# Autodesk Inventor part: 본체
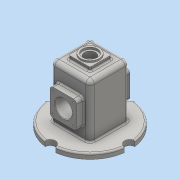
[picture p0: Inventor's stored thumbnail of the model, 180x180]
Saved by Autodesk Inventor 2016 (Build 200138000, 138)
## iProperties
Created: 2018-07
Part Number: 본체
Material: 일반
Document SubType Name: Modeling
Designer: 2-PC06
Density: 1 g/cm^3
Appearance: 기본값
Author: 2-PC06
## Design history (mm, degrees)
sketch "스케치1"
  geometry: C1 r 75 at (0, 0); 1 further point
  constraints: 1 centre point, 1 coincident
  dimensions: "d0" = 150 diameter of C1
extrude "돌출1" new body sketch "스케치1" distance "d1" = 10; taper "d2" = 0 deg
sketch "스케치2"
  geometry: L1 (-37, 37)-(37, 37); L2 (37, 37)-(37, -37); L3 (37, -37)-(-37, -37); L4 (-37, -37)-(-37, 37); L5 (-37, 37)-(37, -37); L6 (37, 37)-(-37, -37); 1 further point
  constraints: 12 end point, 2 midpoint, 2 parallel, 1 horizontal, 1 perpendicular
  dimensions: "d3" = 74 distance of L1.start L1.end; "d4" = 74 distance of L1.end L2.end
extrude "돌출2" join sketch "스케치2" distance "d5" = 100; taper "d6" = 0 deg
sketch "스케치3"
  geometry: L1 (-20, 20)-(20, 20); L2 (20, 20)-(20, -20); L3 (20, -20)-(-20, -20); L4 (-20, -20)-(-20, 20); L5 (-20, 20)-(20, -20); L6 (20, 20)-(-20, -20); 1 further point
  constraints: 12 end point, 2 midpoint, 2 parallel, 1 horizontal, 1 perpendicular
  dimensions: "d7" = 40 distance of L1.start L1.end; "d8" = 40 distance of L1.end L2.end
extrude "돌출3" join sketch "스케치3" distance "d9" = 7; taper "d10" = 0 deg
sketch "스케치4"
  geometry: C1 r 17.5 at (0, 0); 1 further point
  constraints: 1 centre point, 1 coincident
  dimensions: "d11" = 35 diameter of C1
extrude "돌출4" join sketch "스케치4" distance "d12" = 3; taper "d13" = 0 deg
sketch "스케치6"
  geometry: L1 (32, -32)-(-32, -32); L2 (-32, -32)-(-32, 32); L3 (-32, 32)-(32, 32); L4 (32, 32)-(32, -32); L5 (32, -32)-(-32, 32); L6 (-32, -32)-(32, 32); 1 further point
  constraints: 12 end point, 2 midpoint, 2 parallel, 1 horizontal, 1 perpendicular
  dimensions: "d15" = 64 distance of L1.start L1.end; "d16" = 64 distance of L1.end L2.end
extrude "돌출5" cut sketch "스케치6" distance "d17" = 105; taper "d18" = 0 deg
sketch "스케치7"
  geometry: C1 r 10.5 at (0, 0); 1 further point
  constraints: 1 centre point, 1 coincident
  dimensions: "d19" = 21 diameter of C1
extrude "돌출6" cut sketch "스케치7" stored distance "d20" = 105; taper "d21" = 0 deg
sketch "스케치8"
  geometry: C1 r 10.5 at (0, 0) reference; C2 r 14 at (0, 0); 1 further point
  constraints: 1 centre point, 1 coincident
  dimensions: "d22" = 28 diameter of C2
extrude "돌출7" cut sketch "스케치8" distance "d23" = 4; taper "d24" = 0 deg
sketch "스케치10"
  geometry: L1 (12, 70)-(62, 70); L2 (62, 70)-(62, 20); L3 (62, 20)-(12, 20); L4 (12, 20)-(12, 70); L5 (12, 70)-(62, 20); L6 (62, 70)-(12, 20); L7 (-38, -10)-(112, -10) reference; 3 further points
  constraints: 12 end point, 3 midpoint, 2 parallel, 1 horizontal, 1 perpendicular, 1 vertical alignment
  dimensions: "d25" = 50 distance of L1.start L1.end; "d26" = 50 distance of L1.end L2.end; "d27" = 55 distance from line of L7 point (37, 45)
extrude "돌출8" join sketch "스케치10" distance "d28" = 13; taper "d29" = 0 deg
sketch "스케치11"
  geometry: L1 (-32, 0)-(-32, 105) reference; L2 (-32, 55)-(37.636, 55); L3 (-32, 80)-(-25, 80); L4 (-25, 80)-(-25, 55); L5 (25, 55)-(25, 80); L6 (25, 80)-(32, 80); L7 (32, 0)-(32, 105) reference; L8 (-32, 80)-(-32, 55); L9 (32, 80)-(32, 55); 1 further point
  constraints: 14 end point, 9 point on line, 2 horizontal, 1 collinear, 1 parallel, 1 perpendicular
  dimensions: "d30" = 50 diameter of L3 L2; "d31" = 50 diameter of L6 L2 (derived); "d32" = 55 distance from line of point (0, 0) L2; "d33" = 7 distance of L3.start L3.end; "d34" = 7 distance of L5.end L6.end
revolve "회전1" sketch "스케치11" stored, may be unused: angle "d35" = 90 deg
feature "면 기울기1" dims angle "d36" = 20 deg
feature "면 기울기2" dims angle "d37" = 20 deg
sketch "스케치12"
  geometry: L1 (-50, 80)-(-50, 30) reference; L2 (-50, 55)-(50, 55); L3 (50, 80)-(50, 30) reference; L4 (-50, 71)-(50, 71); L5 (50, 55)-(50, 71); L6 (-50, 55)-(-50, 71); 1 further point
  constraints: 8 end point, 2 collinear, 2 midpoint, 2 point on line, 1 perpendicular
  dimensions: "d38" = 32 diameter of L4 L2
revolve "회전2" sketch "스케치12" stored, may be unused: angle "d39" = 90 deg
sketch "스케치13"
  geometry: C1 r 10 at (-75, 0); C2 r 10 at (0, 75); C3 r 10 at (75, 0); C4 r 10 at (0, -75); A1 r 75 centre (0, 0) between (-75, 0) and (0, 75) reference; 1 further point
  constraints: 4 centre point, 4 point on circle, 3 equal radius, 2 horizontal alignment, 2 vertical alignment
  dimensions: "d40" = 20 diameter of C1
extrude "돌출9" cut sketch "스케치13" distance "d41" = 13; taper "d42" = 0 deg
sketch "스케치14"
  geometry: L1 (18, 64)-(56, 64); L2 (56, 64)-(56, 26); L3 (56, 26)-(18, 26); L4 (18, 26)-(18, 64); L5 (18, 64)-(56, 26); L6 (56, 64)-(18, 26); L7 (62, 70)-(12, 70) reference; L8 (12, 70)-(12, 20) reference; C1 r 16 at (37, 45) reference; 5 further points
  constraints: 12 end point, 4 coincident, 2 midpoint, 2 parallel, 1 horizontal, 1 perpendicular
  dimensions: "d43" = 6 distance between parallel lines of L1 L7; "d44" = 6 distance between parallel lines of L8 L4
hole "구멍1" sketch "스케치14" at (18, 64), (56, 64), (56, 26), (18, 26) diameter "d45" = 3.242; stored, may be unused: countersink angle "d49" = 90 deg, drill point angle "d51" = 118 deg; dims "d46" = 8, "d47" = 4, "d48" = 2, "d50" = 10
chamfer "모따기1" distance "d52" = 1; stored, may be unused: second distance "d53" = 2, angle "d54" = 45 deg
fillet "모깎기1" dims "d55" = 3
fillet "모깎기2" dims "d56" = 6
fillet "모깎기3" dims "d57" = 3
fillet "모깎기4" dims "d58" = 8
fillet "모깎기5" dims "d59" = 8
fillet "모깎기6" dims "d60" = 3
fillet "모깎기7" dims "d61" = 3
fillet "모깎기8" dims "d62" = 3
sketch "스케치15"
  geometry: L1 (49.739, 8.998)-(8.261, 8.998); L2 (8.261, 8.998)-(8.261, 15.002); L3 (8.261, 15.002)-(49.739, 15.002); L4 (49.739, 15.002)-(49.739, 8.998); L5 (49.739, 12)-(8.261, 12); L6 (29, 8.998)-(29, 15.002); L7 (-8, 89)-(-8, 0) reference; L8 (11.5, -18)-(46.5, -18) reference; 1 further point
  constraints: 4 end point, 4 midpoint, 2 other
  dimensions: "d63" = 37 distance between parallel lines of L7 L6; "d64" = 30 distance between parallel lines of L5 L8
feature "엠보싱1" sketch "스케치15" dims "d65" = 0.5, "d66" = 0
node "솔리드1"
mirror "대칭1"
mirror "대칭2"
